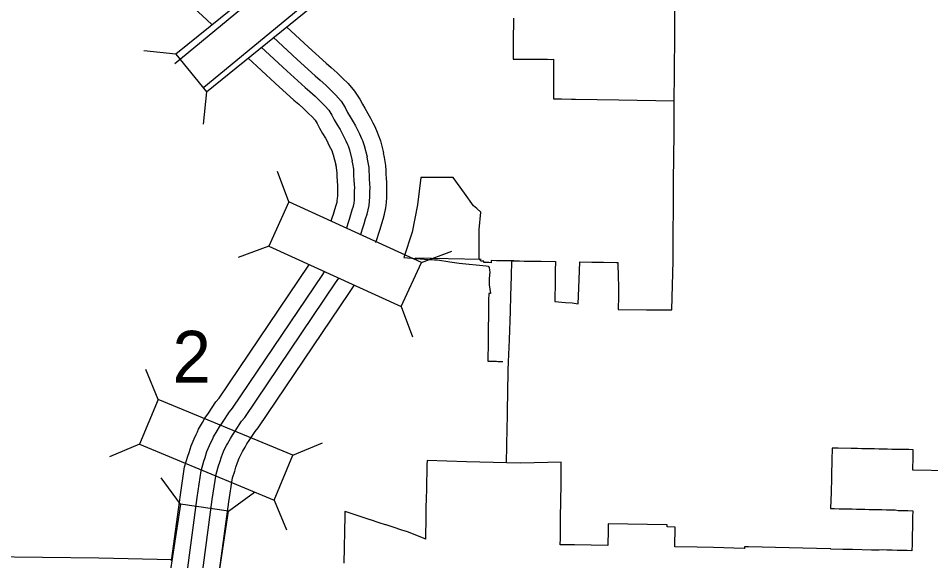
# Model space of a CAD drawing. Extents: x 309389.3 to 309420.2, y 336441.4 to 336461.2.
# Drawn here: x 309391.343 to 309392.47, y 336457.854 to 336458.524 of the extents above; entities that cross this region are included whole.
import ezdxf

# ---------------------------------------------------------------- set-up
doc = ezdxf.new("R2010")
doc.units = 0
for name, color, linetype in [('Level 24', 7, 'Continuous'), ('Level 37', 7, 'Continuous'), ('Level 4', 7, 'Continuous'), ('Level 62', 7, 'Continuous'), ('R_Erosion', 7, 'Continuous')]:
    doc.layers.add(name, color=color, linetype=linetype)

msp = doc.modelspace()

# ---------------------------------------------------------------- linework, layer by layer
at = {"layer": 'Level 24'}
for points in [[(309391.5368, 336458.4684), (309391.7014, 336458.6046)], [(309391.5725, 336458.4389), (309391.7172, 336458.5586)], [(309391.5331, 336457.8551), (309391.443, 336457.857), (309391.1641, 336457.8605)]]:
    msp.add_lwpolyline(points, dxfattribs=at)
at = {"layer": 'Level 37'}
for p, q in [((309391.5382, 336458.4797), (309391.4984, 336458.4838)), ((309391.576, 336458.4331), (309391.5719, 336458.3933)), ((309391.6776, 336458.2972), (309391.6637, 336458.3347)), ((309391.6776, 336458.2972), (309391.6637, 336458.3347)), ((309391.6527, 336458.2426), (309391.6152, 336458.2287)), ((309391.6527, 336458.2426), (309391.6152, 336458.2287)), ((309391.8414, 336458.2224), (309391.8788, 336458.2364)), ((309391.8414, 336458.2224), (309391.8788, 336458.2364)), ((309391.8164, 336458.1679), (309391.8304, 336458.1304)), ((309391.5161, 336458.0532), (309391.5008, 336458.0902)), ((309391.4931, 336457.9978), (309391.4562, 336457.9825)), ((309391.6824, 336457.9844), (309391.7193, 336457.9997)), ((309391.5436, 336457.924), (309391.5198, 336457.9562)), ((309391.6029, 336457.9151), (309391.6351, 336457.9389)), ((309391.6594, 336457.9289), (309391.6747, 336457.892))]:
    msp.add_line(p, q, dxfattribs=at)
for points in [[(309391.576, 336458.4331), (309391.7158, 336458.5465), (309391.678, 336458.5931), (309391.5382, 336458.4797)], [(309391.6527, 336458.2426), (309391.8164, 336458.1679), (309391.8414, 336458.2224), (309391.6776, 336458.2972)], [(309391.6824, 336457.9844), (309391.5161, 336458.0532), (309391.4931, 336457.9978), (309391.6594, 336457.9289)], [(309391.5436, 336457.924), (309391.5168, 336457.746), (309391.5762, 336457.7371), (309391.6029, 336457.9151)]]:
    msp.add_lwpolyline(points, close=True, dxfattribs=at)
at = {"layer": 'Level 4'}
msp.add_lwpolyline([(309391.9152, 336458.2263), (309391.8334, 336458.2276)], dxfattribs=at)
at = {"layer": 'Level 62'}
for points in [[(309392.152, 336458.2244), (309392.1527, 336458.3233), (309392.1532, 336458.3819), (309392.1534, 336458.4117), (309392.1535, 336458.4222), (309392.1537, 336458.455), (309392.1541, 336458.5063), (309392.1542, 336458.5211), (309392.1542, 336458.5237), (309392.1544, 336458.5396)], [(309391.9549, 336458.5244), (309391.9548, 336458.5175), (309391.9546, 336458.5018), (309391.9545, 336458.4738), (309391.9958, 336458.4735), (309391.9968, 336458.4735), (309392.0017, 336458.4733), (309392.0043, 336458.4734), (309392.0043, 336458.4245), (309392.0141, 336458.4244), (309392.0267, 336458.4242), (309392.0316, 336458.4242), (309392.0852, 336458.4233), (309392.1535, 336458.4222)], [(309391.9555, 336458.2243), (309391.9531, 336458.2244), (309391.951, 336458.2244), (309391.9454, 336458.2245), (309391.9397, 336458.2246), (309391.934, 336458.2246), (309391.9273, 336458.2247), (309391.9273, 336458.2241), (309391.9273, 336458.2222), (309391.9244, 336458.2223), (309391.9183, 336458.2224), (309391.9183, 336458.224), (309391.9149, 336458.224), (309391.9139, 336458.2252), (309391.9128, 336458.2265), (309391.9126, 336458.2588), (309391.9126, 336458.2591), (309391.9125, 336458.2633), (309391.9147, 336458.2847), (309391.9098, 336458.289), (309391.9058, 336458.2926), (309391.8943, 336458.3079), (309391.8806, 336458.3273), (309391.871, 336458.3274), (309391.8515, 336458.3273), (309391.8404, 336458.3275), (309391.8366, 336458.2936), (309391.8297, 336458.2599), (309391.8194, 336458.2285), (309391.824, 336458.2281), (309391.8501, 336458.2263), (309391.8575, 336458.2258), (309391.8611, 336458.2257), (309391.8762, 336458.2231), (309391.888, 336458.2216), (309391.9214, 336458.2182), (309391.9237, 336458.2179), (309391.9248, 336458.2163), (309391.9255, 336458.2128), (309391.9258, 336458.2104), (309391.9249, 336458.2027), (309391.9249, 336458.1949), (309391.9264, 336458.184), (309391.9244, 336458.1841), (309391.9243, 336458.176), (309391.9242, 336458.1699), (309391.9241, 336458.1639), (309391.9241, 336458.1579), (309391.924, 336458.1518), (309391.9239, 336458.1458), (309391.9239, 336458.1397), (309391.9238, 336458.1336), (309391.9237, 336458.1276), (309391.9237, 336458.1215), (309391.9236, 336458.1155), (309391.9235, 336458.1094), (309391.9234, 336458.1033), (309391.9235, 336458.1006), (309391.9295, 336458.1005), (309391.934, 336458.1004), (309391.9356, 336458.1003), (309391.9417, 336458.1002)], [(309391.9489, 336458.0999), (309391.9501, 336458.1267), (309391.9512, 336458.1622), (309391.9518, 336458.1811), (309391.9526, 336458.2054), (309391.9531, 336458.2244), (309391.9567, 336458.2243), (309391.9624, 336458.2243), (309391.9681, 336458.2242), (309391.9738, 336458.2241), (309391.9795, 336458.224), (309391.9891, 336458.2239), (309392.0067, 336458.2237), (309392.0066, 336458.2124), (309392.0065, 336458.2031), (309392.0064, 336458.1975), (309392.0063, 336458.1918), (309392.0062, 336458.1821), (309392.0062, 336458.1767), (309392.0061, 336458.1742), (309392.019, 336458.1732), (309392.0275, 336458.1724), (309392.0349, 336458.1713), (309392.0357, 336458.1906), (309392.037, 336458.2232), (309392.0371, 336458.2232), (309392.0518, 336458.2229), (309392.0661, 336458.2227), (309392.082, 336458.2224), (309392.084, 336458.2224), (309392.0844, 336458.2039), (309392.0847, 336458.1939), (309392.0847, 336458.1907), (309392.0846, 336458.1808), (309392.0844, 336458.1645), (309392.1194, 336458.1639), (309392.1507, 336458.1638), (309392.152, 336458.2244)], [(309392.447, 336457.8663), (309392.4468, 336457.8664), (309392.4411, 336457.8665), (309392.4349, 336457.8667), (309392.4287, 336457.8668), (309392.4224, 336457.867), (309392.4162, 336457.8671), (309392.4109, 336457.8673), (309392.4066, 336457.8671), (309392.4033, 336457.8669), (309392.3969, 336457.8671), (309392.3735, 336457.8677), (309392.3642, 336457.868), (309392.3618, 336457.868), (309392.3467, 336457.8683), (309392.3467, 336457.8687), (309392.3461, 336457.8687), (309392.2955, 336457.8699), (309392.2453, 336457.871), (309392.2449, 336457.8711), (309392.2404, 336457.8712), (309392.2404, 336457.8693), (309392.2399, 336457.8693), (309392.2019, 336457.8702), (309392.1816, 336457.8707), (309392.1542, 336457.8713), (309392.1547, 336457.8955), (309392.1447, 336457.8959), (309392.1448, 336457.8984), (309392.0962, 336457.8991), (309392.0718, 336457.8994), (309392.0718, 336457.8974), (309392.0717, 336457.892), (309392.0714, 336457.8727), (309392.0303, 336457.8736), (309392.0128, 336457.8737), (309392.0129, 336457.8818), (309392.013, 336457.892), (309392.0131, 336457.9022), (309392.0132, 336457.9125), (309392.0134, 336457.9226), (309392.0135, 336457.9328), (309392.0137, 336457.9431), (309392.0138, 336457.9533), (309392.0139, 336457.9637), (309392.014, 336457.9757), (309391.9641, 336457.9747), (309391.9464, 336457.9749), (309391.9472, 336458.0176), (309391.9473, 336458.0237), (309391.9474, 336458.0268), (309391.9474, 336458.0297), (309391.9475, 336458.0358), (309391.9476, 336458.0418), (309391.9477, 336458.0479), (309391.9478, 336458.054), (309391.9479, 336458.06), (309391.948, 336458.0661), (309391.9482, 336458.0721), (309391.9483, 336458.0782), (309391.9484, 336458.0856), (309391.9484, 336458.0894), (309391.9489, 336458.0999)], [(309392.3559, 336457.993), (309392.3525, 336457.9931), (309392.3486, 336457.9932), (309392.3482, 336457.9782), (309392.3476, 336457.9597), (309392.3476, 336457.9559), (309392.3471, 336457.9385), (309392.3466, 336457.9185), (309392.3515, 336457.9184), (309392.3572, 336457.9182), (309392.3629, 336457.9181), (309392.3681, 336457.918), (309392.3733, 336457.9179), (309392.3785, 336457.9178), (309392.3838, 336457.9176), (309392.389, 336457.9175), (309392.3942, 336457.9174), (309392.398, 336457.9173), (309392.3994, 336457.9173), (309392.4062, 336457.9171), (309392.41, 336457.9171), (309392.4157, 336457.9169), (309392.4178, 336457.9169), (309392.4209, 336457.9168), (309392.4238, 336457.9167), (309392.4261, 336457.9167), (309392.4298, 336457.9162), (309392.4359, 336457.9161), (309392.442, 336457.9159), (309392.448, 336457.9157), (309392.4479, 336457.9073), (309392.4478, 336457.9067), (309392.4478, 336457.9067), (309392.4477, 336457.9048), (309392.4477, 336457.9035), (309392.4477, 336457.9035), (309392.4476, 336457.9021), (309392.4476, 336457.8952), (309392.4475, 336457.8939), (309392.4474, 336457.8869), (309392.4474, 336457.8869), (309392.4473, 336457.8845), (309392.4473, 336457.8831), (309392.4473, 336457.8831), (309392.4471, 336457.8745), (309392.447, 336457.8663), (309392.4468, 336457.8664), (309392.4411, 336457.8665), (309392.4349, 336457.8667), (309392.4287, 336457.8668), (309392.4224, 336457.867), (309392.4162, 336457.8671), (309392.4109, 336457.8673), (309392.4066, 336457.8671), (309392.4033, 336457.8669), (309392.3969, 336457.8671), (309392.3735, 336457.8677), (309392.3642, 336457.868), (309392.3618, 336457.868), (309392.3467, 336457.8683), (309392.3467, 336457.8687), (309392.3461, 336457.8687), (309392.2955, 336457.8699), (309392.2453, 336457.871), (309392.2449, 336457.8711), (309392.2404, 336457.8712), (309392.2404, 336457.8693), (309392.2399, 336457.8693), (309392.2019, 336457.8702), (309392.1816, 336457.8707), (309392.1542, 336457.8713), (309392.1547, 336457.8955), (309392.1447, 336457.8959), (309392.1448, 336457.8984), (309392.0962, 336457.8991), (309392.0718, 336457.8994), (309392.0718, 336457.8974), (309392.0717, 336457.892), (309392.0714, 336457.8727), (309392.0303, 336457.8736), (309392.0128, 336457.8737), (309392.0129, 336457.8818), (309392.013, 336457.892), (309392.0131, 336457.9022), (309392.0132, 336457.9125), (309392.0134, 336457.9226), (309392.0135, 336457.9328), (309392.0137, 336457.9431), (309392.0138, 336457.9533), (309392.0139, 336457.9637), (309392.014, 336457.9757), (309391.9641, 336457.9747), (309391.9464, 336457.9749), (309391.897, 336457.9761), (309391.8482, 336457.978), (309391.8479, 336457.9725), (309391.8479, 336457.9626), (309391.8475, 336457.952), (309391.8476, 336457.9422), (309391.8471, 336457.9307)], [(309392.4937, 336457.9651), (309392.4482, 336457.9657), (309392.4482, 336457.9696), (309392.4484, 336457.9787), (309392.4485, 336457.9825), (309392.4486, 336457.9903), (309392.4486, 336457.9911), (309392.4433, 336457.9912), (309392.438, 336457.9913), (309392.4327, 336457.9914), (309392.4274, 336457.9915), (309392.4221, 336457.9916), (309392.4168, 336457.9917), (309392.4115, 336457.9918), (309392.4062, 336457.992), (309392.4009, 336457.9921), (309392.3978, 336457.9921), (309392.3956, 336457.9922), (309392.3903, 336457.9923), (309392.385, 336457.9924), (309392.3797, 336457.9925), (309392.3721, 336457.9927), (309392.3559, 336457.993), (309392.3525, 336457.9931), (309392.3486, 336457.9932), (309392.3482, 336457.9782), (309392.3476, 336457.9597), (309392.3476, 336457.9559), (309392.3471, 336457.9385), (309392.3466, 336457.9185), (309392.3515, 336457.9184), (309392.3572, 336457.9182), (309392.3629, 336457.9181), (309392.3681, 336457.918), (309392.3733, 336457.9179), (309392.3785, 336457.9178), (309392.3838, 336457.9176), (309392.389, 336457.9175), (309392.3942, 336457.9174), (309392.398, 336457.9173), (309392.3994, 336457.9173), (309392.4062, 336457.9171), (309392.41, 336457.9171), (309392.4157, 336457.9169), (309392.4178, 336457.9169), (309392.4209, 336457.9168), (309392.4238, 336457.9167), (309392.4261, 336457.9167), (309392.4298, 336457.9162), (309392.4359, 336457.9161)], [(309392.4937, 336457.9651), (309392.4482, 336457.9657), (309392.4482, 336457.9696), (309392.4484, 336457.9787), (309392.4485, 336457.9825), (309392.4486, 336457.9903), (309392.4486, 336457.9911), (309392.4433, 336457.9912), (309392.438, 336457.9913), (309392.4327, 336457.9914), (309392.4274, 336457.9915), (309392.4221, 336457.9916), (309392.4168, 336457.9917), (309392.4115, 336457.9918), (309392.4062, 336457.992), (309392.4009, 336457.9921), (309392.3978, 336457.9921), (309392.3956, 336457.9922), (309392.3903, 336457.9923), (309392.385, 336457.9924), (309392.3797, 336457.9925), (309392.3721, 336457.9927), (309392.3559, 336457.993)], [(309391.8471, 336457.9307), (309391.8469, 336457.9197), (309391.8467, 336457.9092), (309391.8464, 336457.8808), (309391.844, 336457.8818), (309391.8242, 336457.8895), (309391.817, 336457.8919), (309391.8064, 336457.8954), (309391.7977, 336457.8982), (309391.7971, 336457.8984), (309391.7891, 336457.901), (309391.7786, 336457.9045), (309391.778, 336457.9046), (309391.7658, 336457.9086), (309391.7484, 336457.9143), (309391.7469, 336457.9148), (309391.7468, 336457.9093), (309391.7455, 336457.8509)], [(309392.4359, 336457.9161), (309392.442, 336457.9159), (309392.448, 336457.9157), (309392.4479, 336457.9073), (309392.4478, 336457.9067), (309392.4478, 336457.9067), (309392.4477, 336457.9048), (309392.4477, 336457.9035), (309392.4477, 336457.9035), (309392.4476, 336457.9021), (309392.4476, 336457.8952), (309392.4475, 336457.8939), (309392.4474, 336457.8869), (309392.4474, 336457.8869), (309392.4473, 336457.8845), (309392.4473, 336457.8831), (309392.4473, 336457.8831), (309392.4471, 336457.8745), (309392.447, 336457.8663)]]:
    msp.add_lwpolyline(points, dxfattribs=at)
at = {"layer": 'R_Erosion'}
for points in [[(309391.5313, 336458.5643), (309391.5826, 336458.5166)], [(309391.6747, 336458.5137), (309391.7018, 336458.4885), (309391.7238, 336458.4686), (309391.7298, 336458.4635), (309391.7373, 336458.4566), (309391.7439, 336458.4503), (309391.751, 336458.4434), (309391.7588, 336458.4342), (309391.7653, 336458.4241), (309391.7684, 336458.4179), (309391.7713, 336458.413), (309391.7753, 336458.4064), (309391.7784, 336458.4006), (309391.7811, 336458.395), (309391.7836, 336458.3905), (309391.7867, 336458.3836), (309391.788, 336458.3802), (309391.7906, 336458.3727), (309391.7943, 336458.3579)], [(309391.6747, 336458.5137), (309391.7018, 336458.4885), (309391.7238, 336458.4686), (309391.7298, 336458.4635), (309391.7373, 336458.4566), (309391.7439, 336458.4503), (309391.751, 336458.4434), (309391.7588, 336458.4342), (309391.7653, 336458.4241), (309391.7684, 336458.4179), (309391.7713, 336458.413), (309391.7753, 336458.4064), (309391.7784, 336458.4006), (309391.7811, 336458.395), (309391.7836, 336458.3905), (309391.7867, 336458.3836), (309391.788, 336458.3802), (309391.7906, 336458.3727), (309391.7943, 336458.3579)], [(309391.6582, 336458.5006), (309391.6877, 336458.4731), (309391.7101, 336458.4529), (309391.7161, 336458.4478), (309391.7231, 336458.4415), (309391.7293, 336458.4354), (309391.7358, 336458.4291), (309391.742, 336458.4218), (309391.7471, 336458.4138), (309391.7501, 336458.4078), (309391.7534, 336458.4023), (309391.7572, 336458.396), (309391.7599, 336458.3911), (309391.7626, 336458.3855), (309391.7649, 336458.3813), (309391.7675, 336458.3754), (309391.7685, 336458.373), (309391.7706, 336458.3668), (309391.7741, 336458.3528)], [(309391.6582, 336458.5006), (309391.6877, 336458.4731), (309391.7101, 336458.4529), (309391.7161, 336458.4478), (309391.7231, 336458.4415), (309391.7293, 336458.4354), (309391.7358, 336458.4291), (309391.742, 336458.4218), (309391.7471, 336458.4138), (309391.7501, 336458.4078), (309391.7534, 336458.4023), (309391.7572, 336458.396), (309391.7599, 336458.3911), (309391.7626, 336458.3855), (309391.7649, 336458.3813), (309391.7675, 336458.3754), (309391.7685, 336458.373), (309391.7706, 336458.3668), (309391.7741, 336458.3528)], [(309391.6435, 336458.4883), (309391.6749, 336458.4591), (309391.6976, 336458.4386), (309391.7036, 336458.4336), (309391.7101, 336458.4277), (309391.7161, 336458.4218), (309391.7219, 336458.4161), (309391.7268, 336458.4105), (309391.7306, 336458.4044), (309391.7336, 336458.3986), (309391.7372, 336458.3926), (309391.7408, 336458.3866), (309391.743, 336458.3825), (309391.7457, 336458.3769), (309391.7479, 336458.3728), (309391.7501, 336458.368), (309391.7507, 336458.3664), (309391.7524, 336458.3615), (309391.7558, 336458.3481)], [(309391.6435, 336458.4883), (309391.6749, 336458.4591), (309391.6976, 336458.4386), (309391.7036, 336458.4336), (309391.7101, 336458.4277), (309391.7161, 336458.4218), (309391.7219, 336458.4161), (309391.7268, 336458.4105), (309391.7306, 336458.4044), (309391.7336, 336458.3986), (309391.7372, 336458.3926), (309391.7408, 336458.3866), (309391.743, 336458.3825), (309391.7457, 336458.3769), (309391.7479, 336458.3728), (309391.7501, 336458.368), (309391.7507, 336458.3664), (309391.7524, 336458.3615), (309391.7558, 336458.3481)], [(309391.627, 336458.4753), (309391.6608, 336458.4438), (309391.6839, 336458.423), (309391.6898, 336458.4179), (309391.6958, 336458.4125), (309391.7016, 336458.4069), (309391.7067, 336458.4018), (309391.71, 336458.3981), (309391.7125, 336458.3941), (309391.7153, 336458.3885), (309391.7193, 336458.3819), (309391.7227, 336458.3762), (309391.7245, 336458.373), (309391.7271, 336458.3674), (309391.7292, 336458.3635), (309391.7309, 336458.3598), (309391.7312, 336458.3592), (309391.7324, 336458.3556), (309391.7356, 336458.343)], [(309391.7661, 336458.2565), (309391.7668, 336458.2587), (309391.7688, 336458.2651), (309391.7705, 336458.27), (309391.7724, 336458.2764), (309391.7741, 336458.282), (309391.7757, 336458.2874), (309391.7768, 336458.2929), (309391.7773, 336458.2982), (309391.7777, 336458.3037), (309391.7777, 336458.3105), (309391.7778, 336458.3144), (309391.7777, 336458.3198), (309391.7772, 336458.3254), (309391.777, 336458.3304), (309391.7769, 336458.3351), (309391.7766, 336458.3399), (309391.7753, 336458.3481), (309391.7741, 336458.3527)], [(309391.785, 336458.2473), (309391.785, 336458.2476), (309391.7866, 336458.2522), (309391.7886, 336458.2586), (309391.7904, 336458.2637), (309391.7924, 336458.2705), (309391.794, 336458.276), (309391.7959, 336458.2823), (309391.7974, 336458.2898), (309391.7981, 336458.2966), (309391.7985, 336458.303), (309391.7985, 336458.31), (309391.7987, 336458.3143), (309391.7985, 336458.321), (309391.798, 336458.3269), (309391.7978, 336458.3312), (309391.7977, 336458.3359), (309391.7973, 336458.3421), (309391.7957, 336458.3522), (309391.7944, 336458.3577)], [(309391.7299, 336458.274), (309391.731, 336458.2775), (309391.7326, 336458.2821), (309391.7343, 336458.2877), (309391.736, 336458.2934), (309391.7371, 336458.2971), (309391.7374, 336458.2988), (309391.7377, 336458.3014), (309391.7379, 336458.3049), (309391.7379, 336458.3113), (309391.738, 336458.3146), (309391.738, 336458.3176), (309391.7375, 336458.3227), (309391.7372, 336458.329), (309391.7371, 336458.3335), (309391.737, 336458.3355), (309391.7363, 336458.3402), (309391.7355, 336458.3431)], [(309391.7491, 336458.2653), (309391.7508, 336458.271), (309391.7525, 336458.2758), (309391.7542, 336458.2818), (309391.7559, 336458.2874), (309391.7573, 336458.292), (309391.7581, 336458.2957), (309391.7585, 336458.2997), (309391.7587, 336458.3043), (309391.7587, 336458.3109), (309391.7589, 336458.3145), (309391.7588, 336458.3188), (309391.7583, 336458.3241), (309391.758, 336458.3298), (309391.7579, 336458.3344), (309391.7577, 336458.3378), (309391.7567, 336458.3443), (309391.7557, 336458.3482)], [(309391.5328, 336457.854), (309391.5436, 336457.9352), (309391.5488, 336457.9699), (309391.5529, 336457.9833), (309391.5545, 336457.9878), (309391.5569, 336457.9958), (309391.5605, 336458.0045), (309391.563, 336458.0101), (309391.5647, 336458.0133), (309391.5661, 336458.0167), (309391.5711, 336458.0248), (309391.574, 336458.0301), (309391.5782, 336458.0362), (309391.5875, 336458.0504), (309391.5914, 336458.055), (309391.7021, 336458.2192), (309391.7023, 336458.2196)], [(309391.551, 336457.8328), (309391.5642, 336457.9323), (309391.5692, 336457.9652), (309391.5728, 336457.9769), (309391.5743, 336457.9815), (309391.5765, 336457.9888), (309391.5796, 336457.9963), (309391.5817, 336458.0008), (309391.5836, 336458.0044), (309391.5847, 336458.0072), (309391.5891, 336458.0143), (309391.5918, 336458.0192), (309391.5955, 336458.0246), (309391.6042, 336458.0378), (309391.608, 336458.0423), (309391.7194, 336458.2076), (309391.7222, 336458.2118)], [(309391.5701, 336457.8328), (309391.5829, 336457.9296), (309391.5877, 336457.961), (309391.5908, 336457.9712), (309391.5923, 336457.9757), (309391.5944, 336457.9824), (309391.597, 336457.9888), (309391.5987, 336457.9925), (309391.6007, 336457.9962), (309391.6017, 336457.9986), (309391.6055, 336458.0048), (309391.608, 336458.0093), (309391.6113, 336458.0141), (309391.6193, 336458.0264), (309391.6231, 336458.0308), (309391.7352, 336458.1971), (309391.7392, 336458.2032)], [(309391.5907, 336457.8328), (309391.6036, 336457.9267), (309391.6081, 336457.9564), (309391.6107, 336457.9648), (309391.6122, 336457.9694), (309391.614, 336457.9753), (309391.6162, 336457.9806), (309391.6174, 336457.9832), (309391.6195, 336457.9872), (309391.6203, 336457.9891), (309391.6235, 336457.9943), (309391.6258, 336457.9984), (309391.6286, 336458.0026), (309391.636, 336458.0138), (309391.6397, 336458.0181), (309391.7525, 336458.1855), (309391.7582, 336458.1941)]]:
    msp.add_lwpolyline(points, dxfattribs=at)

# ---------------------------------------------------------------- texts
at = {"layer": 'Level 37'}
msp.add_text('2', height=0.064, dxfattribs=at).set_placement((309391.5338, 336458.074))

doc.saveas('drawing.dxf')
